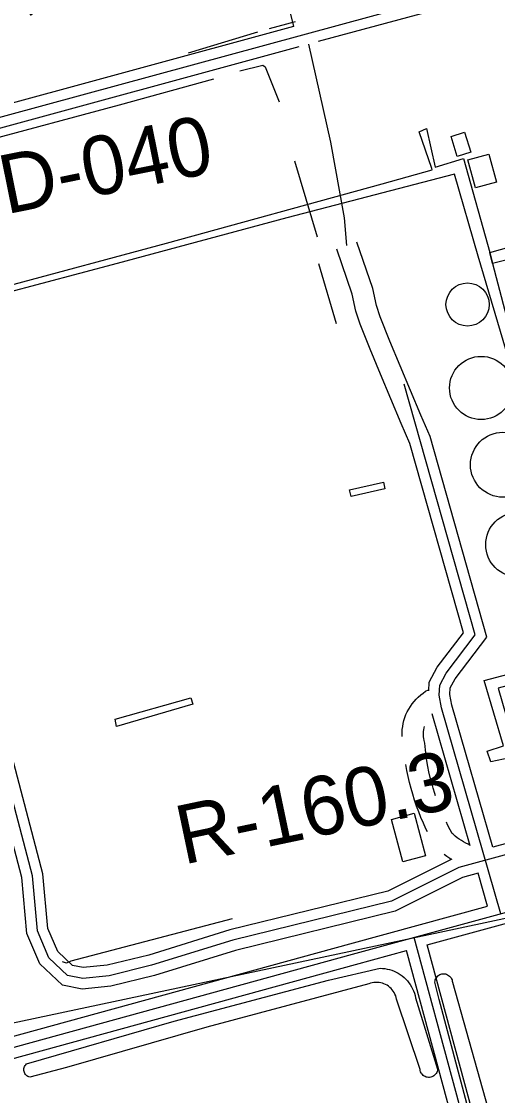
# Model space of a CAD drawing. Extents: x 3419139 to 3457078, y 540382 to 565875.
# Drawn here: x 3439424 to 3440095, y 558838 to 560354 of the extents above; entities that cross this region are included whole.
import ezdxf

# ---------------------------------------------------------------- set-up
doc = ezdxf.new("R2010")
doc.units = 0
for name, color, linetype in [('V-BLDG-OTLN', 7, 'Continuous'), ('V-DOMW-TANK', 7, 'Continuous'), ('V-RIVR-RANG-IDEN', 7, 'Continuous'), ('V-ROAD-CNTR', 7, 'Continuous'), ('V-SITE-OTLN', 7, 'Continuous'), ('V-SITE-VEGE', 7, 'Continuous'), ('V-SURV-IDEN', 7, 'Continuous'), ('V-TOPO-SHOR', 7, 'Continuous'), ('V-UTIL-LINE', 7, 'Continuous')]:
    doc.layers.add(name, color=color, linetype=linetype)

msp = doc.modelspace()

# ---------------------------------------------------------------- linework, layer by layer
at = {"layer": 'V-BLDG-OTLN'}
for points in [[(3440038.2, 560163.3), (3440029.4, 560191.5), (3440048.4, 560197.4), (3440057.1, 560169.2)], [(3440053, 560158.5), (3440082.6, 560166.6), (3440093.3, 560127.1), (3440063.7, 560119.1)], [(3439886.5, 559692.8), (3439934, 559703.5), (3439936.1, 559694.2), (3439888.6, 559683.5)], [(3439961.4, 559168.1), (3439945.3, 559227.9), (3439977.2, 559236.5), (3439993.3, 559176.7)]]:
    msp.add_lwpolyline(points, close=True, dxfattribs=at)
at = {"layer": 'V-DOMW-TANK'}
for centre, radius in [((3440052.7, 559954.3), 30.4), ((3440071.9, 559836.6), 44.6), ((3440102.6, 559728.3), 45.8), ((3440124.1, 559615.5), 45.8)]:
    msp.add_circle(centre, radius, dxfattribs=at)
at = {"layer": 'V-ROAD-CNTR'}
for points in [[(3439807.6, 560346.7), (3439789.9, 560420.5), (3439775.2, 560459.6), (3439766.3, 560495.4)], [(3440334.2, 559239.8), (3440114.8, 559180.2), (3440040.2, 559160), (3439945.5, 559112.4), (3439721.8, 559057.4), (3439607.3, 559022.1), (3439547.4, 559007.3), (3439510.3, 559003.7), (3439488.8, 559007.9), (3439462.4, 559032.8), (3439446.3, 559070.5), (3439439.3, 559148.4), (3439269.7, 559793.9), (3439251.3, 559893.5), (3439248.2, 559955), (3439254.7, 559992.1), (3439281.2, 560138.8), (3439299.2, 560178.9), (3439321.7, 560194.7), (3439353.4, 560207.7), (3440078.2, 560405.3)], [(3439842.8, 560325.6), (3440082.2, 560390.8)], [(3440067.5, 559151.9), (3440045.6, 559145.9), (3439950.7, 559098.3), (3439725.8, 559043), (3439611.3, 559007.7), (3439550, 558992.5), (3439509.6, 558988.5), (3439481.6, 558994.1), (3439449.8, 559024.1), (3439431.5, 559066.8), (3439424.5, 559145.8), (3439255.1, 559790.7), (3439236.4, 559891.8), (3439233.1, 559955.9), (3439239.9, 559994.8), (3439266.8, 560143.3), (3439287.2, 560188.8), (3439314.5, 560208), (3439348.6, 560221.9), (3439807.6, 560347.1)], [(3440030.5, 559171.9), (3439940.2, 559126.6), (3439717.8, 559071.9), (3439603.3, 559036.6), (3439544.9, 559022.2), (3439511, 559018.8), (3439496, 559021.8), (3439475, 559041.6), (3439461, 559074.2), (3439454.1, 559151), (3439284.4, 559797.2), (3439266.3, 559895.3), (3439263.3, 559954.1), (3439269.5, 559989.5), (3439295.6, 560134.4), (3439311.2, 560169), (3439329, 560181.5), (3439358.3, 560193.5), (3439815.3, 560318.1)], [(3439882.5, 560037.4), (3439879.3, 560076.5), (3439860.2, 560183.5), (3439828.8, 560321.5)], [(3439337.9, 558886), (3439890.7, 559037.8), (3440298.7, 559149.2), (3440779.7, 559278.5), (3441232, 559408.4), (3441290.3, 559418.7), (3441333.2, 559434.1), (3441366.9, 559445.9), (3441491, 559493.6), (3441565.2, 559538.3), (3441630.8, 559579.3), (3441672.7, 559604.7), (3441699.1, 559618.6), (3441726.6, 559627.7), (3441821.9, 559657.4), (3442421.5, 559828.3), (3443074, 560013.7), (3443334.7, 560084.3), (3443393.3, 560107.2)], [(3439999.8, 559768), (3439986.9, 559798.1), (3439972.1, 559832.8), (3439957.6, 559867.6), (3439943.3, 559902.5), (3439929.4, 559936.9), (3439924.4, 559952.9), (3439919.1, 559977), (3439896.7, 560042.3)], [(3439971.5, 559758), (3439959.3, 559786.3), (3439944.5, 559821.2), (3439929.9, 559856.1), (3439915.5, 559891.2), (3439901.2, 559926.8), (3439895.4, 559945.1), (3439890.2, 559968.9), (3439868.3, 560032.6)], [(3440099.5, 559094.8), (3440016, 559385.4), (3440012.6, 559403.1), (3440013.5, 559417.5), (3440022.5, 559434.4), (3440063.3, 559488.1), (3439963.4, 559841.8)], [(3440088.2, 559188.6), (3440030.6, 559388.9), (3440027.7, 559404.1), (3440028.3, 559413.3), (3440035.2, 559426.3), (3440079.8, 559485), (3439999.8, 559768)], [(3439998, 559409.4), (3439998.8, 559421.7), (3440009.8, 559442.5), (3440046.9, 559491.2), (3439971.5, 559758)], [(3439960.5, 559344.9), (3439960.5, 559345.9), (3439960.5, 559350.3), (3439960.7, 559354.7), (3439961.3, 559359), (3439962, 559363.3), (3439963.1, 559367.5), (3439964.4, 559371.7), (3439965.9, 559375.7), (3439967.7, 559379.7), (3439969.8, 559383.6), (3439972.1, 559387.3), (3439974.6, 559390.9), (3439977.3, 559394.3), (3439980.2, 559397.5), (3439983.3, 559400.6), (3439986.6, 559403.5), (3439990, 559406.1), (3439993.6, 559408.6), (3439997.4, 559410.8), (3439998.1, 559411.2)], [(3440056.4, 559190.5), (3440002.9, 559376.7)], [(3440007.7, 559261), (3440006.6, 559264.3), (3440004.2, 559271.9), (3440002.1, 559279.5), (3440000.1, 559287.2), (3439998.3, 559294.9), (3439996.8, 559302.7), (3439995.4, 559310.5), (3439994.2, 559318.3), (3439993.3, 559326.2), (3439992.4, 559335.4), (3439991.4, 559339.4), (3439990.9, 559341.9), (3439990.6, 559344.4), (3439990.5, 559346.9), (3439990.5, 559349.4), (3439990.6, 559352), (3439990.9, 559354.5), (3439991.4, 559357), (3439991.9, 559359)], [(3439996.2, 559210.3), (3439994, 559214.7), (3439990.4, 559222.6), (3439987, 559230.6), (3439983.8, 559238.7), (3439980.8, 559246.8), (3439978, 559255.1), (3439975.4, 559263.4), (3439973.1, 559271.7), (3439970.9, 559280.2), (3439969, 559288.6), (3439967.3, 559297.1), (3439965.9, 559305.3)], [(3440315.9, 559250.4), (3440110.9, 559194.7), (3440088.2, 559188.6)], [(3440056.1, 559191.8), (3440053.6, 559192.8), (3440050.3, 559194.4), (3440047.1, 559196.1), (3440044, 559198), (3440041, 559200), (3440038, 559202.1), (3440035.2, 559204.4), (3440032.5, 559206.9), (3440031.2, 559208.2), (3440028.3, 559213.4), (3440024.6, 559220.4), (3440022.9, 559224.1)], [(3440029.7, 559171.5), (3440027.9, 559172.6), (3440023.7, 559175.4), (3440019.6, 559178.4), (3440019.5, 559178.6)], [(3440080.9, 559105.3), (3440067.5, 559151.9)], [(3439995.7, 559050.9), (3440302.6, 559134.8), (3440343.2, 559145.7)], [(3439333.9, 558900.4), (3439886.8, 559052.3), (3440080.9, 559105.3)], [(3440094.8, 558627), (3439977.3, 559061.5)], [(3439341.9, 558871.5), (3439894.7, 559023.3), (3439966.8, 559043)], [(3440118.9, 558480.4), (3439966.8, 559043)], [(3440147.3, 558490.5), (3439995.7, 559050.9)]]:
    msp.add_lwpolyline(points, dxfattribs=at)
at = {"layer": 'V-SITE-OTLN'}
msp.add_lwpolyline([(3441215.1, 559326.2), (3441157, 559313.7), (3440359, 559142.1), (3440035.7, 559073.3), (3439387.2, 558935.4), (3438963.4, 560917.5), (3438901.6, 561206.6), (3440756.7, 561603.2), (3440702.2, 561858.4), (3440994.1, 561929.6), (3441319.4, 561990.3), (3441403.1, 561599), (3441739.1, 560028.5), (3441741.8, 560014.4), (3441372, 559935.4), (3441469.3, 559480.5), (3441489.7, 559384.9)], close=True, dxfattribs=at)
at = {"layer": 'V-SITE-VEGE'}
msp.add_lwpolyline([(3439431.1, 558883), (3439639.3, 558943.5), (3439856.5, 559001.2), (3439929.5, 559017.9), (3439932.9, 559017.7), (3439936.2, 559017.4), (3439939.5, 559016.8), (3439942.7, 559016), (3439945.9, 559015), (3439949.1, 559013.8), (3439952.1, 559012.4), (3439955, 559010.8), (3439957.9, 559009), (3439960.6, 559007), (3439963.2, 559004.9), (3439965.6, 559002.6), (3439967.9, 559000.1), (3439970, 558997.5), (3439971.9, 558994.8), (3439973.7, 558991.9), (3439975.2, 558988.9), (3439976.6, 558985.9), (3439977.8, 558982.7), (3439978.7, 558979.5), (3439979.5, 558976.3), (3440010.5, 558875.6), (3440010.2, 558874), (3440009.8, 558872.5), (3440009.2, 558871), (3440008.4, 558869.6), (3440007.5, 558868.3), (3440006.3, 558867.1), (3440005.1, 558866.2), (3440003.7, 558865.3), (3440002.2, 558864.7), (3440000.7, 558864.2), (3439999.1, 558864), (3439997.5, 558864), (3439995.9, 558864.1), (3439994.3, 558864.5), (3439992.8, 558865.1), (3439991.4, 558865.9), (3439990.1, 558866.8), (3439989, 558867.9), (3439987.9, 558869.1), (3439987.1, 558870.5), (3439986.4, 558872), (3439986, 558873.5), (3439985.7, 558875.1), (3439952.6, 558974.4), (3439952.1, 558976.8), (3439951.4, 558979.1), (3439950.4, 558981.3), (3439949.3, 558983.5), (3439948, 558985.6), (3439946.6, 558987.5), (3439945, 558989.3), (3439943.2, 558991), (3439941.3, 558992.5), (3439939.3, 558993.9), (3439937.1, 558995), (3439934.9, 558996), (3439932.6, 558996.8), (3439930.3, 558997.4), (3439927.9, 558997.8), (3439925.4, 558998), (3439923, 558998), (3439920.6, 558997.8), (3439918.2, 558997.4), (3439915.8, 558996.8), (3439913.6, 558996), (3439685.4, 558934.9), (3439487.5, 558877.7), (3439435.8, 558864.3), (3439434.4, 558864.7), (3439433, 558865.3), (3439431.7, 558866.1), (3439430.6, 558867), (3439429.6, 558868.1), (3439428.7, 558869.4), (3439428, 558870.7), (3439427.6, 558872.1), (3439427.3, 558873.6), (3439427.3, 558875.1), (3439427.4, 558876.6), (3439427.8, 558878.1), (3439428.4, 558879.4), (3439429.1, 558880.7), (3439430, 558881.9)], close=True, dxfattribs=at)
msp.add_lwpolyline([(3440053.6, 558819.9), (3440012.6, 558973.7), (3440006.6, 558998.5), (3440006.8, 559000.1), (3440007.2, 559001.7), (3440007.9, 559003.2), (3440008.7, 559004.6), (3440009.7, 559005.9), (3440010.8, 559007.1), (3440012.1, 559008), (3440013.6, 559008.9), (3440015.1, 559009.5), (3440016.6, 559009.9), (3440018.3, 559010.1), (3440019.9, 559010.1), (3440021.5, 559009.9), (3440023.1, 559009.4), (3440024.6, 559008.8), (3440026, 559007.9), (3440027.3, 559006.9), (3440028.4, 559005.8), (3440029.4, 559004.5), (3440030.2, 559003), (3440030.8, 559001.5), (3440031.2, 558999.9), (3440031.4, 558998.3), (3440089.2, 558792.1)], dxfattribs=at)
at = {"layer": 'V-TOPO-SHOR'}
for p, q in [((3439773.6, 560343.5), (3439810.1, 560353.6)), ((3439659.2, 560309.6), (3439757, 560338.8)), ((3439808.6, 560156.9), (3439840.7, 560049.6)), ((3439842.8, 560012.3), (3439867.7, 559927.5))]:
    msp.add_line(p, q, dxfattribs=at)
for points in [[(3439731.7, 560284), (3439764.2, 560292.2), (3439767.6, 560289.5), (3439787.3, 560240.1)], [(3439303.2, 560161.1), (3439322.3, 560171.4), (3439365.7, 560183.5), (3439562.2, 560235.8), (3439694.9, 560272.8)], [(3439720.9, 559087.6), (3439493.4, 559027.9), (3439487.2, 559025.2), (3439481.8, 559027.1)]]:
    msp.add_lwpolyline(points, dxfattribs=at)
at = {"layer": 'V-UTIL-LINE'}
msp.add_line((3439557.9, 559358.9), (3439555.9, 559369.2), dxfattribs=at)
for points in [[(3439401.4, 559979.9), (3439628.5, 560040.9), (3439932.4, 560124.7), (3440002.7, 560144.2), (3440002.2, 560146.2), (3439984.7, 560197.9), (3439994.6, 560202.4), (3440007.1, 560148.3), (3440046.8, 560160.2), (3440083.9, 560027.6), (3440087.7, 560012.2), (3440172.5, 559689.4), (3440234.7, 559457.6), (3440067.6, 560022.6), (3440034.4, 560138.3), (3439797.8, 560076.5), (3439558.6, 560012.1), (3439399.5, 559969.9)], [(3440280.4, 560060.3), (3440087.7, 560012.2), (3440083.9, 560027.6), (3440285.9, 560084.4)], [(3440640.5, 559815.9), (3440677.9, 559826.1), (3440684.9, 559800.8), (3440624.7, 559777.9), (3440646.6, 559664.6), (3440638.1, 559662.8), (3440608.1, 559770.9), (3440519.3, 559745.4), (3440567, 559543.5), (3440570.3, 559534.7), (3440637.4, 559289.2), (3440386, 559216.9), (3440271.7, 559186), (3440199, 559440.6), (3440095.8, 559412.9), (3440118.4, 559334.9), (3440151.4, 559312.4), (3440156.6, 559291.3), (3440147.1, 559287.9), (3440142.4, 559301.5), (3440121.2, 559316.5), (3440085.4, 559309.2), (3440080.4, 559324.3)], [(3440080.4, 559324.3), (3440103.2, 559331.5), (3440076.1, 559424), (3440284, 559478.9)], [(3439555.9, 559369.2), (3439662.8, 559399.4), (3439665.5, 559390.5), (3439557.9, 559358.9)]]:
    msp.add_lwpolyline(points, dxfattribs=at)

# ---------------------------------------------------------------- texts
at = {"layer": 'V-RIVR-RANG-IDEN'}
for s, rotation, p in [('D-040', 11.4413, (3439402.3, 560081.4)), ('R-160.3', 11.8915, (3439652.1, 559163.9))]:
    msp.add_text(s, height=83, rotation=rotation, dxfattribs=at).set_placement(p)
at = {"layer": 'V-SURV-IDEN'}
msp.add_text('3505+46.0', height=100, rotation=37.0582, dxfattribs=at).set_placement((3439179.9, 560151.4))

doc.saveas('drawing.dxf')
